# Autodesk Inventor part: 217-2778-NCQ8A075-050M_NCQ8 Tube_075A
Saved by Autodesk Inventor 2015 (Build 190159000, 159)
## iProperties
Created: 2014-11
Part Number: 217-2778-NCQ8A075-050M_NCQ8 Tube_075A
Material: Generic
Document SubType Name: Modeling
Designer: User
Density: 1 g/cm^3
Appearance: Default
Author: User
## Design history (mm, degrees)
node "217-2778-NCQ8A075-050M_NCQ8 Tube_075A.ipt1"
node "056-250 Collar Chamfer"
node "Base1"
